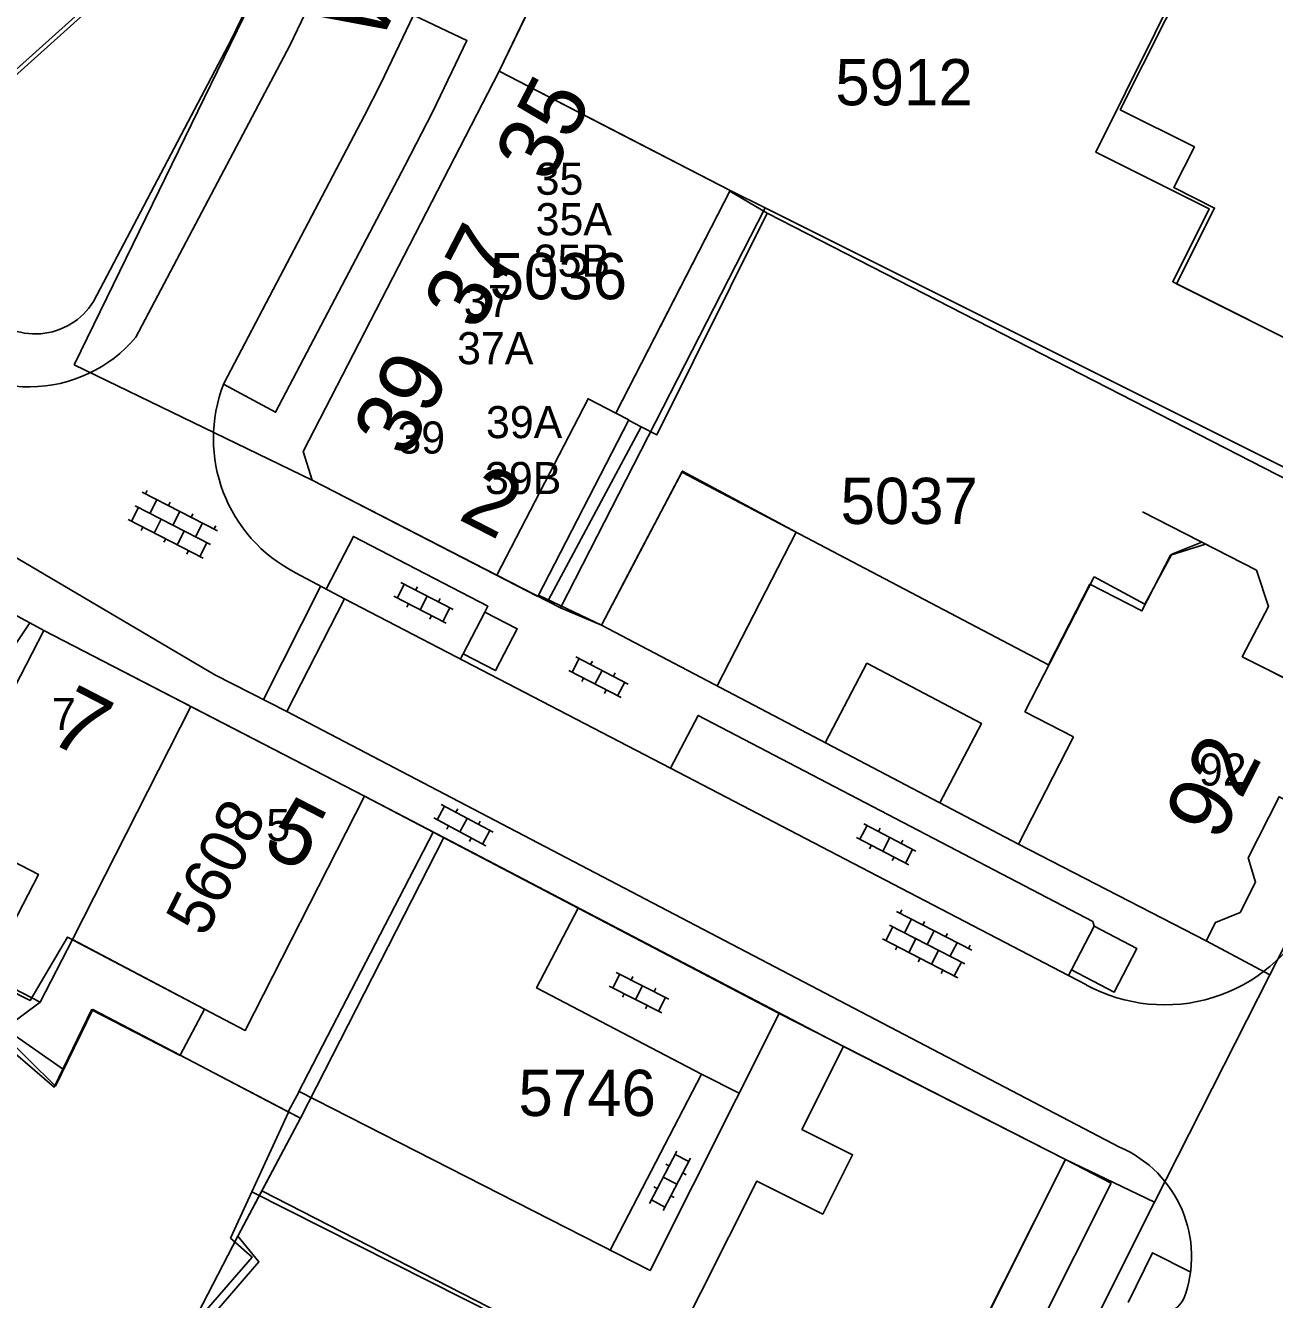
# Model space of a CAD drawing. Extents: x 148816 to 151297, y 399515 to 402500.
# Drawn here: x 150303.76 to 150352.43, y 399632.21 to 399681.86 of the extents above; entities that cross this region are included whole.
import ezdxf

# ---------------------------------------------------------------- set-up
doc = ezdxf.new("R2010")
doc.units = 0
for name, color, linetype in [('B01 Hoofdgebouw  [D] Norm', 7, 'Continuous'), ('B01 Hoofdgebouw  [T] Norm', 7, 'Continuous'), ('B01 hoofgebouw', 7, 'Continuous'), ('G01 perceelsgrens', 7, 'Continuous'), ('S02 Open verharding  Norm', 7, 'Continuous'), ('T04 Haag heg  [D] Gem', 7, 'Continuous'), ('V00 Kant verharding algemeen  [T] Norm', 7, 'Continuous'), ('V00 Kant verharding algemeen secundair  [T] Gem', 7, 'Continuous'), ('V06 Kant onverhard  [T] Gem', 7, 'Continuous'), ('Z01 perceelnummer', 7, 'Continuous'), ('Z02 huisnummer', 7, 'Continuous'), ('Z02 Huisnummer  [Tekst] Norm', 7, 'Continuous'), ('Z06 straatnaam', 7, 'Continuous')]:
    doc.layers.add(name, color=color, linetype=linetype)

msp = doc.modelspace()

# ---------------------------------------------------------------- linework, layer by layer
at = {"layer": 'B01 Hoofdgebouw  [D] Norm'}
for p, q in [((150348.426, 399661.257), (150349.596, 399661.723)), ((150348.426, 399661.257), (150347.374, 399659.308)), ((150345.405, 399660.371), (150342.701, 399655.106)), ((150347.374, 399659.308), (150345.405, 399660.371)), ((150342.701, 399655.106), (150344.598, 399654.132)), ((150344.598, 399654.132), (150342.45, 399649.95))]:
    msp.add_line(p, q, dxfattribs=at)
for points in [[(150348.929, 399683.883), (150345.466, 399676.921), (150349.884, 399674.705), (150348.464, 399671.87), (150354.41, 399668.89)], [(150330.708, 399656.121), (150333.787, 399662.112), (150329.355, 399664.489), (150328.53, 399662.92)], [(150302.18, 399653.84), (150299.474, 399648.595), (150303.054, 399646.736), (150302.061, 399644.805), (150303.94, 399643.863), (150305.399, 399646.336), (150310.74, 399643.53)], [(150297.63, 399636.71), (150302.515, 399642.517), (150304.876, 399640.481), (150306.327, 399643.505), (150309.785, 399641.72)], [(150293.39, 399601.01), (150294.828, 399602.658), (150289.212, 399607.425), (150293.181, 399611.997), (150294.349, 399611.08), (150306.738, 399625.101), (150306.941, 399624.999), (150307.323, 399625.837), (150306.384, 399626.702), (150312.591, 399633.865), (150311.754, 399634.603), (150314.014, 399639.517)], [(150312.581, 399636.401), (150330.444, 399627.392), (150330.496, 399627.466), (150334.72, 399625.32)]]:
    msp.add_lwpolyline(points, dxfattribs=at)
at = {"layer": 'B01 Hoofdgebouw  [T] Norm'}
for p, q in [((150314.58, 399665.26), (150322.22, 399680.07)), ((150322.22, 399680.07), (150331.225, 399675.426)), ((150331.225, 399675.426), (150326.76, 399666.75)), ((150327.266, 399666.489), (150326.76, 399666.75)), ((150327.266, 399666.489), (150323.722, 399659.61)), ((150314.93, 399664.14), (150314.58, 399665.26)), ((150314.93, 399664.14), (150323.722, 399659.61)), ((150328.53, 399662.92), (150326.2, 399658.49)), ((150349.596, 399661.723), (150351.73, 399660.629)), ((150352.2, 399659.22), (150351.73, 399660.63)), ((150351.17, 399657.26), (150352.2, 399659.22)), ((150304.47, 399658.28), (150302.18, 399653.84)), ((150316.97, 399651.82), (150304.47, 399658.28)), ((150326.2, 399658.49), (150342.45, 399649.95)), ((150353.65, 399656.01), (150351.17, 399657.26)), ((150312.32, 399642.7), (150316.97, 399651.82)), ((150351.4, 399649.42), (150352.61, 399651.8)), ((150342.45, 399649.95), (150349.77, 399646.19)), ((150351.69, 399648.47), (150351.4, 399649.42)), ((150351.09, 399647.29), (150351.69, 399648.47)), ((150350.13, 399646.9), (150351.09, 399647.29)), ((150349.77, 399646.19), (150350.13, 399646.9)), ((150309.79, 399641.73), (150310.74, 399643.53)), ((150310.74, 399643.53), (150312.32, 399642.7)), ((150333.13, 399643.35), (150328.1, 399633.34)), ((150344.29, 399637.67), (150333.13, 399643.35)), ((150313.99, 399639.53), (150309.79, 399641.73)), ((150314.42, 399640.32), (150313.99, 399639.53)), ((150328.1, 399633.34), (150314.42, 399640.32)), ((150339.52, 399628.18), (150344.29, 399637.67))]:
    msp.add_line(p, q, dxfattribs=at)
for points in [[(150300.2, 399677.28), (150282.27, 399697.22), (150290.31, 399704.45), (150292.47, 399702.05), (150294.16, 399703.56), (150298.854, 399698.331), (150296.981, 399696.646), (150301.07, 399692.098), (150302.91, 399693.752), (150307.77, 399688.4), (150306.1, 399686.89), (150308.24, 399684.5), (150300.2, 399677.28), (150282.27, 399697.22)], [(150334.921, 399653.907), (150336.548, 399657.004), (150341.011, 399654.658), (150339.384, 399651.561)]]:
    msp.add_lwpolyline(points, dxfattribs=at)
at = {"layer": 'B01 hoofgebouw'}
for points in [[(150297.5, 399699.84), (150294.16, 399703.56), (150292.47, 399702.05), (150290.31, 399704.45), (150282.27, 399697.22), (150300.2, 399677.28), (150308.24, 399684.5), (150306.1, 399686.89), (150307.77, 399688.4), (150304.41, 399692.1)], [(150354.41, 399668.89), (150348.617, 399671.793), (150350.095, 399674.742), (150348.509, 399675.537), (150349.306, 399677.126), (150346.419, 399678.573), (150349.06, 399683.841)], [(150314.93, 399664.14), (150314.58, 399665.26), (150322.22, 399680.07), (150326.66, 399677.78)], [(150326.66, 399677.78), (150331.225, 399675.426), (150329.05, 399671.2)], [(150329.05, 399671.2), (150326.76, 399666.75), (150325.68, 399667.31), (150322.13, 399660.43), (150314.93, 399664.14)], [(150349.741, 399661.649), (150348.377, 399661.218), (150347.261, 399659.045), (150345.237, 399660.085), (150343.623, 399656.943), (150329.334, 399664.453), (150328.53, 399662.92)], [(150328.53, 399662.92), (150327.532, 399661.022), (150326.2, 399658.49), (150342.45, 399649.95), (150349.77, 399646.19), (150350.13, 399646.9), (150351.09, 399647.29), (150351.69, 399648.47), (150351.4, 399649.42), (150352.61, 399651.8), (150353.01, 399651.59), (150354.28, 399654.07), (150354.9, 399654.31), (150354.29, 399656.21), (150353.65, 399656.01), (150351.17, 399657.26), (150352.2, 399659.22), (150351.73, 399660.63), (150347.28, 399662.91)], [(150344.29, 399637.67), (150333.13, 399643.35), (150328.1, 399633.34), (150314.42, 399640.32), (150313.99, 399639.53), (150309.79, 399641.73), (150310.74, 399643.53), (150312.32, 399642.7), (150316.97, 399651.82), (150304.47, 399658.28), (150302.18, 399653.84)], [(150302.18, 399653.84), (150300.556, 399650.692), (150304.261, 399648.777), (150302.246, 399644.878), (150304.333, 399643.799), (150305.591, 399646.235), (150310.74, 399643.53)], [(150297.63, 399636.71), (150302.788, 399642.637), (150304.925, 399640.529), (150306.386, 399643.513), (150309.79, 399641.73)], [(150335.641, 399642.072), (150334.017, 399638.841), (150335.988, 399637.85), (150334.826, 399635.538), (150332.26, 399636.828), (150328.989, 399630.321), (150331.47, 399629.074), (150330.631, 399627.406), (150334.72, 399625.32)], [(150313.99, 399639.53), (150314.47, 399639.278), (150312.034, 399634.685), (150312.853, 399633.676), (150306.653, 399626.501), (150307.311, 399625.722), (150294.665, 399611.07)], [(150334.72, 399625.32), (150338.672, 399623.304), (150339.15, 399623.06), (150341.3, 399627.27), (150339.52, 399628.18), (150344.29, 399637.67)]]:
    msp.add_lwpolyline(points, dxfattribs=at)
at = {"layer": 'G01 perceelsgrens'}
for points in [[(150322.22, 399680.07), (150327.928, 399691.949)], [(150316.32, 399690.523), (150315.791, 399691.152), (150313.562, 399689.243), (150307.044, 399683.224), (150298.085, 399675.163)], [(150316.32, 399690.523), (150305.651, 399668.634)], [(150314.93, 399664.14), (150314.58, 399665.26), (150322.22, 399680.07)], [(150332.587, 399674.744), (150331.225, 399675.426), (150322.22, 399680.07)], [(150332.587, 399674.744), (150324.61, 399659.165)], [(150360.408, 399660.833), (150332.587, 399674.744)], [(150305.651, 399668.634), (150314.93, 399664.14)], [(150324.61, 399659.165), (150322.13, 399660.43), (150314.93, 399664.14)], [(150303.926, 399658.573), (150296.43, 399662.612), (150295.687, 399661.972)], [(150360.408, 399660.833), (150352.251, 399644.862)], [(150352.251, 399644.862), (150349.77, 399646.19), (150342.45, 399649.95), (150326.2, 399658.49), (150324.61, 399659.165)], [(150303.926, 399658.573), (150296.916, 399648.116), (150292.59, 399641.88), (150290.607, 399639.054)], [(150310.201, 399655.318), (150304.47, 399658.28), (150303.926, 399658.573)], [(150310.201, 399655.318), (150305.591, 399646.235), (150304.333, 399643.799), (150302.96, 399642.767)], [(150320.056, 399650.209), (150316.97, 399651.82), (150310.201, 399655.318)], [(150320.056, 399650.209), (150314.47, 399639.278)], [(150347.751, 399636.003), (150344.29, 399637.67), (150335.641, 399642.072), (150320.056, 399650.209)], [(150352.251, 399644.862), (150347.751, 399636.003)], [(150314.47, 399639.278), (150306.386, 399643.513), (150305.243, 399641.179), (150302.96, 399642.767)], [(150314.47, 399639.278), (150312.971, 399636.45)], [(150312.971, 399636.45), (150312.034, 399634.685), (150309.701, 399630.161)], [(150312.971, 399636.45), (150326.503, 399629.512), (150330.808, 399627.315), (150329.911, 399625.673), (150337.86, 399621.69), (150340.027, 399620.593)], [(150340.027, 399620.593), (150347.751, 399636.003)]]:
    msp.add_lwpolyline(points, dxfattribs=at)
at = {"layer": 'S02 Open verharding  Norm'}
for p, q in [((150311.239, 399662.16), (150308.305, 399663.672)), ((150308.439, 399663.604), (150308.507, 399663.737)), ((150310.964, 399661.627), (150308.03, 399663.139)), ((150308.883, 399663.374), (150308.608, 399662.841)), ((150309.327, 399663.145), (150309.396, 399663.279)), ((150310.689, 399661.094), (150307.755, 399662.606)), ((150307.889, 399662.537), (150308.164, 399663.07)), ((150308.778, 399662.079), (150309.053, 399662.612)), ((150309.497, 399662.383), (150309.772, 399662.916)), ((150310.216, 399662.687), (150310.285, 399662.821)), ((150308.333, 399662.308), (150308.265, 399662.175)), ((150309.667, 399661.621), (150309.941, 399662.154)), ((150310.386, 399661.925), (150310.661, 399662.458)), ((150311.105, 399662.229), (150311.174, 399662.362)), ((150309.222, 399661.85), (150309.153, 399661.716)), ((150310.555, 399661.162), (150310.83, 399661.696)), ((150310.111, 399661.392), (150310.042, 399661.258)), ((150318.384, 399660.146), (150320.431, 399659.098)), ((150318.111, 399659.612), (150320.158, 399658.564)), ((150318.244, 399659.544), (150318.518, 399660.078)), ((150319.031, 399659.983), (150318.963, 399659.85)), ((150319.408, 399659.622), (150319.134, 399659.088)), ((150318.689, 399659.316), (150318.621, 399659.183)), ((150319.921, 399659.527), (150319.853, 399659.394)), ((150320.024, 399658.632), (150320.298, 399659.166)), ((150319.579, 399658.86), (150319.511, 399658.727)), ((150325.061, 399656.656), (150325.338, 399657.188)), ((150325.205, 399657.257), (150327.244, 399656.195)), ((150324.928, 399656.725), (150326.967, 399655.663)), ((150325.851, 399657.09), (150325.781, 399656.957)), ((150326.225, 399656.726), (150325.947, 399656.194)), ((150326.737, 399656.628), (150326.668, 399656.495)), ((150325.504, 399656.425), (150325.435, 399656.292)), ((150326.834, 399655.732), (150327.111, 399656.264)), ((150326.391, 399655.963), (150326.321, 399655.83)), ((150319.807, 399650.906), (150320.091, 399651.435)), ((150319.959, 399651.506), (150321.985, 399650.417)), ((150320.603, 399651.33), (150320.532, 399651.198)), ((150319.675, 399650.977), (150321.701, 399649.888)), ((150320.972, 399650.961), (150320.688, 399650.433)), ((150321.483, 399650.857), (150321.412, 399650.725)), ((150336.554, 399650.676), (150336.277, 399650.144)), ((150338.46, 399649.681), (150336.421, 399650.745)), ((150320.248, 399650.669), (150320.177, 399650.537)), ((150321.128, 399650.196), (150321.057, 399650.064)), ((150321.569, 399649.959), (150321.853, 399650.488)), ((150338.183, 399649.149), (150336.144, 399650.213)), ((150336.998, 399650.444), (150337.067, 399650.577)), ((150337.163, 399649.681), (150337.441, 399650.213)), ((150336.651, 399649.779), (150336.72, 399649.912)), ((150337.884, 399649.982), (150337.953, 399650.115)), ((150338.327, 399649.75), (150338.05, 399649.218)), ((150337.537, 399649.317), (150337.606, 399649.45)), ((150340.637, 399645.818), (150337.703, 399647.33)), ((150337.837, 399647.262), (150337.905, 399647.395)), ((150337.287, 399646.195), (150337.562, 399646.728)), ((150340.362, 399645.285), (150337.428, 399646.797)), ((150338.281, 399647.032), (150338.006, 399646.499)), ((150338.725, 399646.803), (150338.794, 399646.937)), ((150340.087, 399644.752), (150337.153, 399646.264)), ((150338.176, 399645.737), (150338.451, 399646.27)), ((150338.895, 399646.041), (150339.17, 399646.574)), ((150339.614, 399646.345), (150339.683, 399646.479)), ((150337.731, 399645.966), (150337.663, 399645.833)), ((150339.065, 399645.279), (150339.339, 399645.812)), ((150339.784, 399645.583), (150340.059, 399646.116)), ((150340.503, 399645.887), (150340.572, 399646.02)), ((150338.62, 399645.508), (150338.551, 399645.374)), ((150339.953, 399644.82), (150340.228, 399645.354)), ((150326.643, 399644.351), (150326.914, 399644.886)), ((150326.78, 399644.954), (150328.833, 399643.915)), ((150327.428, 399644.794), (150327.36, 399644.661)), ((150339.509, 399645.05), (150339.44, 399644.916)), ((150326.509, 399644.419), (150328.562, 399643.38)), ((150327.807, 399644.435), (150327.535, 399643.899)), ((150328.32, 399644.343), (150328.253, 399644.209)), ((150327.089, 399644.125), (150327.022, 399643.991)), ((150328.428, 399643.448), (150328.699, 399643.983)), ((150327.982, 399643.673), (150327.914, 399643.54)), ((150328.078, 399635.958), (150329.14, 399637.998)), ((150329.603, 399637.587), (150329.071, 399637.865)), ((150328.61, 399635.68), (150329.672, 399637.72)), ((150328.707, 399637.49), (150328.84, 399637.421)), ((150328.609, 399636.978), (150329.141, 399636.7)), ((150329.372, 399637.144), (150329.505, 399637.075)), ((150328.245, 399636.603), (150328.378, 399636.534)), ((150328.679, 399635.813), (150328.147, 399636.091)), ((150328.91, 399636.257), (150329.043, 399636.188))]:
    msp.add_line(p, q, dxfattribs=at)
at = {"layer": 'T04 Haag heg  [D] Gem'}
for p, q in [((150332.659, 399674.543), (150358.434, 399661.325)), ((150324.141, 399659.472), (150327.746, 399666.21)), ((150314.403, 399640.294), (150319.642, 399650.42))]:
    msp.add_line(p, q, dxfattribs=at)
for points in [[(150331.21, 399675.398), (150332.659, 399674.543)], [(150327.746, 399666.21), (150328.355, 399665.904), (150332.659, 399674.543)], [(150327.746, 399666.21), (150327.26, 399666.476)]]:
    msp.add_lwpolyline(points, dxfattribs=at)
at = {"layer": 'V00 Kant verharding algemeen  [T] Norm'}
for p, q in [((150328.76, 399693.68), (150322.22, 399680.07)), ((150323.747, 399659.659), (150326.2, 399658.49)), ((150333.13, 399643.35), (150316.97, 399651.82)), ((150346.06, 399636.74), (150344.29, 399637.67)), ((150341.3, 399627.27), (150346.06, 399636.74))]:
    msp.add_line(p, q, dxfattribs=at)
for points in [[(150311.485, 399667.9), (150316.974, 399678.353), (150317.606, 399679.598), (150318.319, 399681.089), (150346.039, 399739.165), (150350.575, 399744.179), (150363.602, 399771.718)], [(150328.523, 399711.267), (150314.054, 399681.082), (150308.064, 399669.709)], [(150306.411, 399671.098), (150311.786, 399681.318), (150316.616, 399691.322), (150316.09, 399691.6)], [(150346.387, 399638.151), (150313.947, 399655.125), (150311.135, 399656.556), (150297.321, 399664.702)], [(150314.285, 399660.53), (150316.191, 399659.514), (150328.896, 399652.913), (150344.398, 399644.842), (150345.109, 399644.467)], [(150321.664, 399659), (150320.816, 399657.37), (150322.073, 399656.717), (150322.92, 399658.346), (150321.664, 399659)], [(150325.29, 399647.459), (150323.674, 399644.354), (150330.099, 399640.987)], [(150345.402, 399646.758), (150344.515, 399645.064), (150346.183, 399644.191), (150347.07, 399645.885), (150345.402, 399646.758)], [(150326.537, 399634.138), (150330.099, 399640.987)], [(150346.733, 399632.097), (150347.68, 399634.036), (150349.15, 399633.294)]]:
    msp.add_lwpolyline(points, dxfattribs=at)
for centre, radius, start, end in [((150304.142, 399672.51), 2.672, 220.8815, 328.1039), ((150303.902, 399673.212), 5.44, 220.918, 319.9132), ((150316.959, 399665.763), 5.876, 158.6725, 242.9329), ((150348.153, 399650.068), 6.375, 241.4797, 332.8274), ((150344.566, 399633.893), 4.631, 339.1551, 66.8457), ((150348.039, 399632.633), 0.939, 240.2353, 335.5905)]:
    msp.add_arc(centre, radius, start, end, dxfattribs=at)
at = {"layer": 'V00 Kant verharding algemeen secundair  [T] Gem'}
for points in [[(150311.477, 399667.885), (150313.505, 399666.782), (150318.536, 399676.384), (150319.627, 399678.5), (150320.961, 399681.268), (150318.878, 399682.26)], [(150315.258, 399659.996), (150313.029, 399655.591)], [(150316.191, 399659.514), (150313.947, 399655.125)]]:
    msp.add_lwpolyline(points, dxfattribs=at)
at = {"layer": 'V06 Kant onverhard  [T] Gem'}
for points in [[(150315.481, 399659.893), (150316.539, 399661.944), (150321.781, 399659.222), (150321.662, 399658.999)], [(150320.716, 399657.178), (150320.816, 399657.37)], [(150328.896, 399652.913), (150329.974, 399654.973), (150345.357, 399646.939), (150345.399, 399646.757)], [(150344.398, 399644.842), (150344.515, 399645.064)], [(150331.571, 399640.247), (150330.099, 399640.987)]]:
    msp.add_lwpolyline(points, dxfattribs=at)

# ---------------------------------------------------------------- texts
at = {"layer": 'Z01 perceelnummer'}
for s, p in [('5912', (150335.317, 399678.745)), ('5036', (150321.846, 399671.187)), ('5037', (150335.519, 399662.431)), ('5746', (150322.969, 399639.362))]:
    msp.add_text(s, height=1.8, dxfattribs=at).set_placement(p)
msp.add_text('5608', height=1.8, rotation=63.1774, dxfattribs=at).set_placement((150310.763, 399646.284))
at = {"layer": 'Z02 huisnummer'}
for s, rotation, p in [('35', 62.7431, (150324.162, 399675.656)), ('37', 62.7431, (150321.381, 399669.885)), ('39', 62.7431, (150318.633, 399664.938)), ('2', 332.7431, (150320.568, 399662.64)), ('7', 332.6659, (150304.554, 399654.013)), ('92', 63.0764, (150350.286, 399649.989)), ('5', 332.6659, (150312.912, 399649.693))]:
    msp.add_text(s, height=2.5, rotation=rotation, dxfattribs=at).set_placement(p)
at = {"layer": 'Z02 Huisnummer  [Tekst] Norm'}
for s, p in [('35', (150323.639, 399675.26)), ('35A', (150323.639, 399673.683)), ('35B', (150323.564, 399672.068)), ('37', (150320.84, 399670.496)), ('37A', (150320.577, 399668.656)), ('39A', (150321.703, 399665.775)), ('39', (150318.25, 399665.175)), ('39B', (150321.665, 399663.597)), ('7', (150304.79, 399654.4)), ('92', (150349.481, 399652.238)), ('5', (150313.145, 399650.08))]:
    msp.add_text(s, height=1.25, dxfattribs=at).set_placement(p)
at = {"layer": 'Z06 straatnaam'}
msp.add_text('WILHELMINASTRAAT', height=2.5, rotation=64.2289, dxfattribs=at).set_placement((150317.541, 399681.079))

doc.saveas('drawing.dxf')
